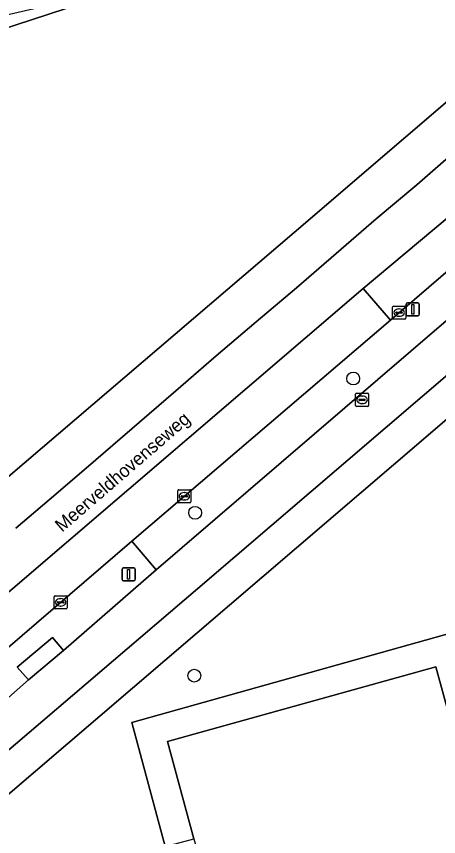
# Model space of a CAD drawing. Extents: x 159053 to 160042, y 380449 to 381423.
# Drawn here: x 159116.5 to 159148.7, y 381158.5 to 381220.9 of the extents above; entities that cross this region are included whole.
import ezdxf

# ---------------------------------------------------------------- set-up
doc = ezdxf.new("R2010")
doc.units = 0
for name, color, linetype in [('IMGEO_Berm_groen', 7, 'Continuous'), ('IMGEO_Boom', 7, 'Continuous'), ('IMGEO_Fietspad_gesloten', 7, 'Continuous'), ('IMGEO_Groenvoorziening', 7, 'Continuous'), ('IMGEO_Kolk', 7, 'Continuous'), ('IMGEO_Lichtmast', 7, 'Continuous'), ('IMGEO_Openbare_ruimte_label', 7, 'Continuous'), ('IMGEO_OVBaan_gesloten', 7, 'Continuous'), ('IMGEO_Pand', 7, 'Continuous'), ('IMGEO_Rijbaan_regionaal_gesloten', 7, 'Continuous'), ('IMGEO_Rioolput', 7, 'Continuous'), ('IMGEO_Voetpad_gesloten', 7, 'Continuous'), ('IMGEO_Voetpad_open', 7, 'Continuous')]:
    doc.layers.add(name, color=color, linetype=linetype)

msp = doc.modelspace()

# ---------------------------------------------------------------- linework, layer by layer
at = {"layer": 'IMGEO_Berm_groen'}
for points in [[(159067.683, 381207.534), (159068.006, 381205.749), (159067.649, 381205.712), (159072.161, 381177.995), (159076.23, 381154.565), (159076.846, 381155.047), (159077.383, 381157.182), (159077.742, 381157.092), (159077.174, 381154.834), (159077.912, 381153.94), (159078.121, 381154.104), (159079.399, 381155.036), (159109.432, 381180.391), (159137.659, 381204.458), (159189.014, 381248.453)], [(159198.149, 381243.375), (159196.536, 381241.932), (159158.845, 381209.673), (159149.731, 381201.872), (159144.985, 381197.81), (159125.306, 381180.977), (159127.177, 381178.813), (159129.142, 381180.518), (159151.57, 381199.758), (159154.961, 381202.667), (159160.659, 381207.528), (159189.61, 381232.226)], [(159132.509, 381225.511), (159128.088, 381224.063), (159102.136, 381215.563)]]:
    msp.add_lwpolyline(points, dxfattribs=at)
at = {"layer": 'IMGEO_Boom'}
for centre in [(159142.161, 381193.358), (159130.127, 381183.145), (159130.066, 381170.76)]:
    msp.add_circle(centre, 0.489, dxfattribs=at)
at = {"layer": 'IMGEO_Fietspad_gesloten'}
for points in [[(159203.02, 381243.648), (159199.551, 381240.945), (159193.266, 381235.559), (159189.61, 381232.226), (159160.659, 381207.528), (159154.961, 381202.667), (159151.57, 381199.758), (159129.142, 381180.518), (159127.177, 381178.813), (159126.193, 381177.959), (159120.101, 381172.671), (159117.461, 381170.437), (159112.235, 381165.849), (159109.222, 381163.321), (159105.75, 381160.281)], [(159108.979, 381159.184), (159130.347, 381177.389), (159158.844, 381201.787)]]:
    msp.add_lwpolyline(points, dxfattribs=at)
at = {"layer": 'IMGEO_Groenvoorziening'}
for points in [[(159172.151, 381181.759), (159168.702, 381185.792), (159158.254, 381197.977), (159147.691, 381188.91), (159105.47, 381152.828)], [(159121.982, 381156.173), (159127.859, 381157.764), (159125.308, 381167.186), (159149.74, 381174.045), (159151.875, 381166.058), (159152.853, 381166.328), (159154.809, 381166.867), (159158.633, 381153.175), (159162.065, 381151.254), (159162.515, 381149.573), (159169.259, 381151.47), (159167.96, 381156.207), (159163.076, 381174.02), (159172.151, 381181.759)]]:
    msp.add_lwpolyline(points, dxfattribs=at)
at = {"layer": 'IMGEO_Kolk'}
for p, q in [((159145.151, 381197.945), (159145.151, 381198.797)), ((159145.226, 381198.871), (159146.078, 381198.871)), ((159145.639, 381198.651), (159145.664, 381198.651)), ((159146.152, 381198.797), (159146.152, 381197.945)), ((159145.41, 381198.365), (159145.41, 381198.377)), ((159145.848, 381198.328), (159145.45, 381198.328)), ((159145.453, 381198.414), (159145.851, 381198.414)), ((159145.662, 381198.091), (159145.637, 381198.091)), ((159145.894, 381198.377), (159145.894, 381198.365)), ((159146.078, 381197.871), (159145.226, 381197.871)), ((159128.809, 381183.976), (159128.809, 381184.828)), ((159128.884, 381184.902), (159129.736, 381184.902)), ((159129.81, 381184.828), (159129.81, 381183.976)), ((159129.068, 381184.396), (159129.068, 381184.408)), ((159129.506, 381184.359), (159129.108, 381184.359)), ((159129.111, 381184.445), (159129.509, 381184.445)), ((159129.297, 381184.682), (159129.322, 381184.682)), ((159129.552, 381184.408), (159129.552, 381184.396)), ((159129.736, 381183.902), (159128.884, 381183.902)), ((159129.32, 381184.122), (159129.295, 381184.122)), ((159119.391, 381175.908), (159119.391, 381176.76)), ((159119.466, 381176.834), (159120.318, 381176.834)), ((159120.392, 381176.76), (159120.392, 381175.908)), ((159119.65, 381176.328), (159119.65, 381176.34)), ((159120.088, 381176.291), (159119.69, 381176.291)), ((159119.693, 381176.377), (159120.091, 381176.377)), ((159119.879, 381176.614), (159119.904, 381176.614)), ((159120.134, 381176.34), (159120.134, 381176.328)), ((159120.318, 381175.834), (159119.466, 381175.834)), ((159119.902, 381176.054), (159119.877, 381176.054))]:
    msp.add_line(p, q, dxfattribs=at)
for points in [[(159145.151, 381197.945), (159145.151, 381198.797)], [(159145.226, 381198.871), (159146.078, 381198.871)], [(159146.152, 381198.797), (159146.152, 381197.945)], [(159146.078, 381197.871), (159145.226, 381197.871)], [(159128.809, 381183.976), (159128.809, 381184.828)], [(159128.884, 381184.902), (159129.736, 381184.902)], [(159129.81, 381184.828), (159129.81, 381183.976)], [(159129.736, 381183.902), (159128.884, 381183.902)], [(159119.391, 381175.908), (159119.391, 381176.76)], [(159119.466, 381176.834), (159120.318, 381176.834)], [(159120.392, 381176.76), (159120.392, 381175.908)], [(159120.318, 381175.834), (159119.466, 381175.834)]]:
    msp.add_lwpolyline(points, dxfattribs=at)
for centre, radius, start, end in [((159145.228, 381198.795), 0.0765, 91.55205, 178.44795), ((159145.228, 381198.795), 0.0765, 91.55205, 178.44795), ((159146.076, 381198.795), 0.0765, 1.55205, 88.44795), ((159146.076, 381198.795), 0.0765, 1.55205, 88.44795), ((159145.228, 381197.947), 0.0765, 181.55205, 268.44795), ((159145.228, 381197.947), 0.0765, 181.55205, 268.44795), ((159145.45, 381198.374), 0.0403, 85.87752, 175.75265), ((159145.447, 381198.364), 0.0366, 178.93798, 274.71019), ((159145.851, 381198.371), 0.043, 264.86636, 352.45326), ((159145.855, 381198.376), 0.0386, 1.73085, 96.63898), ((159146.076, 381197.947), 0.0765, 271.55205, 358.44795), ((159146.076, 381197.947), 0.0765, 271.55205, 358.44795), ((159128.886, 381184.826), 0.0765, 91.55205, 178.44795), ((159128.886, 381184.826), 0.0765, 91.55205, 178.44795), ((159129.734, 381184.826), 0.0765, 1.55205, 88.44795), ((159129.734, 381184.826), 0.0765, 1.55205, 88.44795), ((159129.108, 381184.405), 0.0403, 85.87752, 175.75265), ((159129.105, 381184.395), 0.0366, 178.93798, 274.71019), ((159129.509, 381184.402), 0.043, 264.86636, 352.45326), ((159129.513, 381184.407), 0.0386, 1.73085, 96.63898), ((159128.886, 381183.978), 0.0765, 181.55205, 268.44795), ((159128.886, 381183.978), 0.0765, 181.55205, 268.44795), ((159129.734, 381183.978), 0.0765, 271.55205, 358.44795), ((159129.734, 381183.978), 0.0765, 271.55205, 358.44795), ((159119.468, 381176.758), 0.0765, 91.55205, 178.44795), ((159119.468, 381176.758), 0.0765, 91.55205, 178.44795), ((159120.316, 381176.758), 0.0765, 1.55205, 88.44795), ((159120.316, 381176.758), 0.0765, 1.55205, 88.44795), ((159119.69, 381176.337), 0.0403, 85.87752, 175.75265), ((159119.687, 381176.327), 0.0366, 178.93798, 274.71019), ((159120.091, 381176.334), 0.043, 264.86636, 352.45326), ((159120.095, 381176.339), 0.0386, 1.73085, 96.63898), ((159119.468, 381175.91), 0.0765, 181.55205, 268.44795), ((159119.468, 381175.91), 0.0765, 181.55205, 268.44795), ((159120.316, 381175.91), 0.0765, 271.55205, 358.44795), ((159120.316, 381175.91), 0.0765, 271.55205, 358.44795)]:
    msp.add_arc(centre, radius, start, end, dxfattribs=at)
for centre, major_axis, ratio, start_param, end_param in [((159145.638, 381198.371), (-0.387, 0.002), 0.722429, 4.712389, 7.853982), ((159145.663, 381198.371), (-0.39, 0.002), 0.717154, 1.570796, 4.712389), ((159129.296, 381184.402), (-0.387, 0.002), 0.722429, 4.712389, 7.853982), ((159129.321, 381184.402), (-0.39, 0.002), 0.717154, 1.570796, 4.712389), ((159119.878, 381176.334), (-0.387, 0.002), 0.722429, 4.712389, 7.853982), ((159119.903, 381176.334), (-0.39, 0.002), 0.717154, 1.570796, 4.712389)]:
    msp.add_ellipse(centre, major_axis=major_axis, ratio=ratio, start_param=start_param, end_param=end_param, dxfattribs=at)
at = {"layer": 'IMGEO_Lichtmast'}
for p, q in [((159146.192, 381198.218), (159146.192, 381199.018)), ((159146.192, 381199.018), (159146.192, 381198.218)), ((159146.292, 381199.118), (159147.082, 381199.118)), ((159147.082, 381199.118), (159146.292, 381199.118)), ((159147.182, 381199.018), (159147.182, 381198.218)), ((159147.182, 381198.218), (159147.182, 381199.018)), ((159147.082, 381198.118), (159146.292, 381198.118)), ((159146.292, 381198.118), (159147.082, 381198.118)), ((159124.571, 381178.063), (159124.571, 381178.863)), ((159124.571, 381178.863), (159124.571, 381178.063)), ((159124.671, 381178.963), (159125.461, 381178.963)), ((159125.461, 381178.963), (159124.671, 381178.963)), ((159125.561, 381178.863), (159125.561, 381178.063)), ((159125.561, 381178.063), (159125.561, 381178.863)), ((159125.461, 381177.963), (159124.671, 381177.963)), ((159124.671, 381177.963), (159125.461, 381177.963))]:
    msp.add_line(p, q, dxfattribs=at)
for points in [[(159146.612, 381198.993), (159146.762, 381198.993), (159146.762, 381198.243), (159146.612, 381198.243), (159146.612, 381198.993)], [(159124.991, 381178.838), (159125.141, 381178.838), (159125.141, 381178.088), (159124.991, 381178.088), (159124.991, 381178.838)]]:
    msp.add_lwpolyline(points, dxfattribs=at)
for centre, start, end in [((159146.292, 381199.018), 90, 180), ((159146.292, 381199.018), 90, 180), ((159147.082, 381199.018), 0, 90), ((159147.082, 381199.018), 360, 90), ((159146.292, 381198.218), 180, 270), ((159146.292, 381198.218), 180, 270), ((159147.082, 381198.218), 270, 0), ((159147.082, 381198.218), 270, 0), ((159124.671, 381178.863), 90, 180), ((159124.671, 381178.863), 90, 180), ((159125.461, 381178.863), 0, 90), ((159125.461, 381178.863), 360, 90), ((159124.671, 381178.063), 180, 270), ((159124.671, 381178.063), 180, 270), ((159125.461, 381178.063), 270, 0), ((159125.461, 381178.063), 270, 0)]:
    msp.add_arc(centre, 0.1, start, end, dxfattribs=at)
at = {"layer": 'IMGEO_OVBaan_gesloten'}
for points in [[(159125.306, 381180.977), (159144.985, 381197.81), (159142.906, 381200.205), (159089.567, 381154.567), (159090.156, 381153.792)], [(159103.97, 381162.819), (159107.317, 381165.55), (159125.306, 381180.977)]]:
    msp.add_lwpolyline(points, dxfattribs=at)
at = {"layer": 'IMGEO_Pand'}
msp.add_lwpolyline([(159150.446, 381163.897), (159150.512, 381163.915), (159148.439, 381171.433), (159128.03, 381165.753), (159130.025, 381158.35), (159134.583, 381142.54), (159135.221, 381140.226), (159155.464, 381145.813)], close=True, dxfattribs=at)
at = {"layer": 'IMGEO_Rijbaan_regionaal_gesloten'}
for points in [[(159189.014, 381248.453), (159137.659, 381204.458), (159109.432, 381180.391)], [(159116.495, 381181.964), (159119.531, 381184.564), (159122.583, 381187.178), (159128.654, 381192.427), (159131.73, 381195.076), (159134.776, 381197.662), (159137.841, 381200.265), (159140.864, 381202.871), (159143.9, 381205.494), (159146.999, 381208.096), (159150.02, 381210.741), (159153.078, 381213.34), (159156.098, 381215.954), (159159.13, 381218.561), (159162.167, 381221.149), (159168.263, 381226.412), (159174.317, 381231.634), (159177.379, 381234.249), (159180.443, 381236.862), (159183.448, 381239.478)], [(159183.448, 381239.478), (159180.443, 381236.862), (159177.379, 381234.249), (159174.317, 381231.634), (159168.263, 381226.412), (159162.167, 381221.149), (159159.13, 381218.561), (159156.098, 381215.954), (159153.078, 381213.34), (159150.02, 381210.741), (159146.999, 381208.096), (159143.9, 381205.494), (159140.864, 381202.871), (159137.841, 381200.265), (159134.776, 381197.662), (159131.73, 381195.076), (159128.654, 381192.427), (159122.583, 381187.178), (159119.531, 381184.564), (159116.495, 381181.964)], [(159089.567, 381154.567), (159142.906, 381200.205), (159149.308, 381205.554), (159155.363, 381210.741), (159161.534, 381215.995), (159167.468, 381221.145), (159173.664, 381226.433), (159179.748, 381231.662), (159188.08, 381238.831)], [(159102.136, 381215.563), (159128.088, 381224.063), (159117.87, 381221.476), (159113.783, 381220.545), (159109.697, 381219.613), (159101.793, 381218.13), (159093.69, 381216.609), (159085.77, 381215.275), (159077.83, 381214.059), (159073.802, 381213.442), (159069.899, 381212.844), (159065.995, 381212.247), (159062.092, 381211.649), (159061.799, 381211.604), (159062.166, 381208.545), (159067.417, 381209.298), (159084.084, 381211.644)]]:
    msp.add_lwpolyline(points, dxfattribs=at)
msp.add_lwpolyline([(159196.536, 381241.932), (159198.149, 381243.375), (159196.902, 381246.438), (159188.08, 381238.831), (159179.748, 381231.662), (159173.664, 381226.433), (159167.468, 381221.145), (159161.534, 381215.995), (159155.363, 381210.741), (159149.308, 381205.554), (159142.906, 381200.205), (159144.985, 381197.81), (159149.731, 381201.872), (159158.845, 381209.673)], close=True, dxfattribs=at)
at = {"layer": 'IMGEO_Rioolput'}
for p, q in [((159142.333, 381191.312), (159142.333, 381192.164)), ((159142.408, 381192.238), (159143.26, 381192.238)), ((159142.592, 381191.732), (159142.592, 381191.744)), ((159143.03, 381191.695), (159142.632, 381191.695)), ((159142.635, 381191.781), (159143.033, 381191.781)), ((159142.821, 381192.018), (159142.846, 381192.018)), ((159143.076, 381191.744), (159143.076, 381191.732)), ((159143.334, 381192.164), (159143.334, 381191.312)), ((159143.26, 381191.238), (159142.408, 381191.238)), ((159142.844, 381191.458), (159142.819, 381191.458))]:
    msp.add_line(p, q, dxfattribs=at)
for points in [[(159142.333, 381191.312), (159142.333, 381192.164)], [(159142.408, 381192.238), (159143.26, 381192.238)], [(159143.334, 381192.164), (159143.334, 381191.312)], [(159143.26, 381191.238), (159142.408, 381191.238)]]:
    msp.add_lwpolyline(points, dxfattribs=at)
for centre, radius, start, end in [((159142.41, 381192.162), 0.0765, 91.55205, 178.44795), ((159142.41, 381192.162), 0.0765, 91.55205, 178.44795), ((159142.632, 381191.741), 0.0403, 85.87752, 175.75265), ((159142.629, 381191.731), 0.0366, 178.93798, 274.71019), ((159143.033, 381191.738), 0.043, 264.86636, 352.45326), ((159143.037, 381191.743), 0.0386, 1.73085, 96.63898), ((159143.258, 381192.162), 0.0765, 1.55205, 88.44795), ((159143.258, 381192.162), 0.0765, 1.55205, 88.44795), ((159142.41, 381191.314), 0.0765, 181.55205, 268.44795), ((159142.41, 381191.314), 0.0765, 181.55205, 268.44795), ((159143.258, 381191.314), 0.0765, 271.55205, 358.44795), ((159143.258, 381191.314), 0.0765, 271.55205, 358.44795)]:
    msp.add_arc(centre, radius, start, end, dxfattribs=at)
for centre, major_axis, ratio, start_param, end_param in [((159142.82, 381191.738), (-0.387, 0.002), 0.722429, 4.712389, 7.853982), ((159142.845, 381191.738), (-0.39, 0.002), 0.717154, 1.570796, 4.712389)]:
    msp.add_ellipse(centre, major_axis=major_axis, ratio=ratio, start_param=start_param, end_param=end_param, dxfattribs=at)
at = {"layer": 'IMGEO_Voetpad_gesloten'}
msp.add_lwpolyline([(159120.101, 381172.671), (159119.288, 381173.648), (159116.591, 381171.408), (159117.461, 381170.437)], close=True, dxfattribs=at)
at = {"layer": 'IMGEO_Voetpad_open'}
for points in [[(159147.691, 381188.91), (159158.254, 381197.977), (159159.622, 381199.152), (159199.656, 381233.519), (159201.154, 381233.903), (159209.72, 381236.419), (159211.127, 381238.462), (159209.158, 381239.776)], [(159202.543, 381239.42), (159197.05, 381234.658), (159195.92, 381233.637), (159182.496, 381222.154), (159158.844, 381201.787), (159130.347, 381177.389), (159108.979, 381159.184)], [(159105.47, 381152.828), (159147.691, 381188.91)], [(159158.67, 381145.252), (159157.836, 381148.256), (159152.853, 381166.328), (159151.875, 381166.058), (159149.74, 381174.045), (159125.308, 381167.186), (159127.859, 381157.764), (159130.025, 381158.35), (159128.03, 381165.753), (159148.439, 381171.433), (159150.512, 381163.915), (159150.446, 381163.897), (159155.464, 381145.813), (159135.221, 381140.226), (159134.583, 381142.54), (159123.394, 381139.418), (159123.313, 381139.396), (159124.153, 381136.349), (159124.172, 381136.281)]]:
    msp.add_lwpolyline(points, dxfattribs=at)
msp.add_lwpolyline([(159126.193, 381177.959), (159127.177, 381178.813), (159125.306, 381180.977), (159107.317, 381165.55), (159109.222, 381163.321), (159112.235, 381165.849), (159117.461, 381170.437), (159116.591, 381171.408), (159119.288, 381173.648), (159120.101, 381172.671)], close=True, dxfattribs=at)

# ---------------------------------------------------------------- texts
at = {"layer": 'IMGEO_Openbare_ruimte_label'}
msp.add_text('Meerveldhovenseweg', height=1, rotation=40.86241, dxfattribs=at).set_placement((159120.002, 381181.628))

doc.saveas('drawing.dxf')
